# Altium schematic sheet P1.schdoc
size 297 x 209 mm; Symbol: Drawing-Symbol_A4; Company: 嘉立创EDA; Version: V1.0; Page Size: A4; @Project Name: 模拟前端处理电路; @Update Date: 2026-04-09; @Create Date: 2026-04-09; Device: Drawing-Symbol_A4; @Board Name: Board1; @Page Name: P1; @Create Time: 13:26:56; @Page Count: 1; @Page No: 1; @Schematic Name: Schematic1; @Update Time: 13:26:56; @Assembly Variant: Basic; Border: 1; Title Block Position: 3; Size: A4; Width: 1170; Height: 825; Region Start: 1; X Region Count: 6; Y Region Count: 4; Blade Width: 10; Title Block: 1
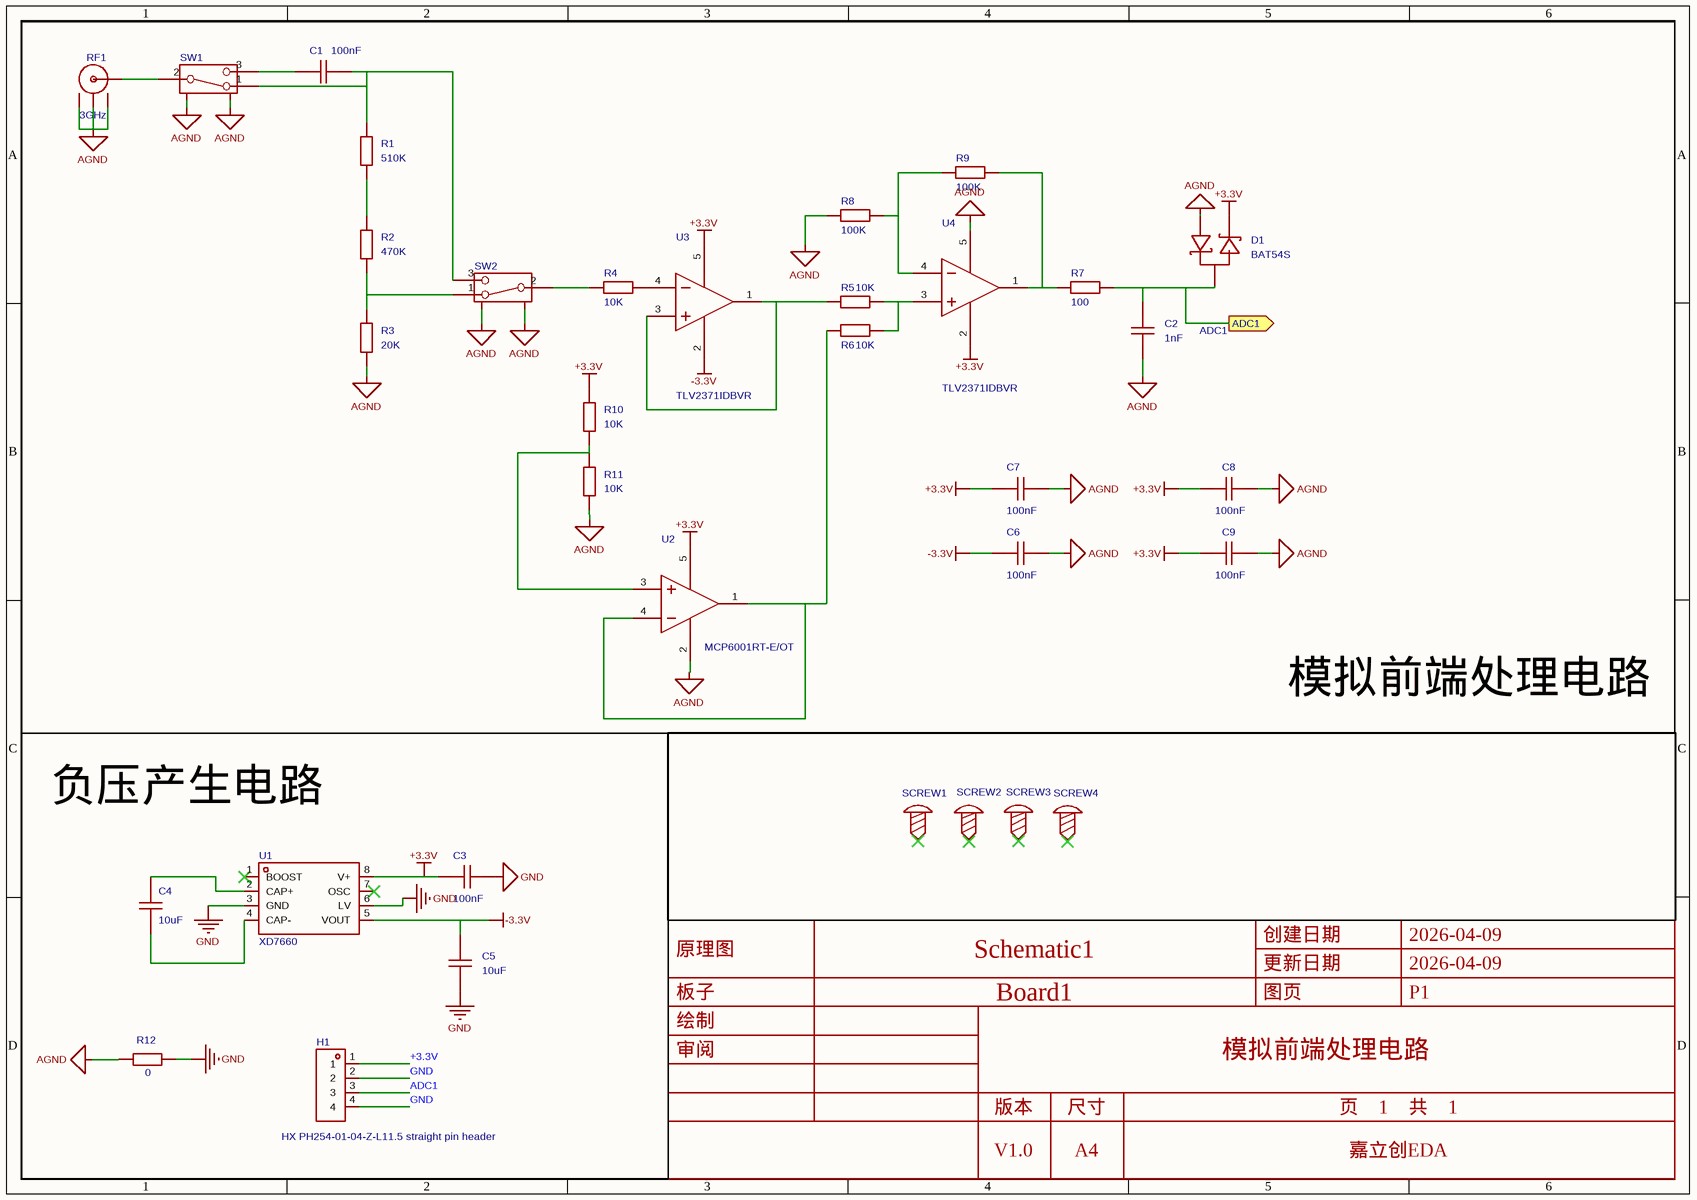
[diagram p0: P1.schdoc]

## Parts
C1  100nF  [C0603]
C2  1nF  [C0603]
C3  100nF  [C0603]
C4  10uF  [C0603]
C5  10uF  [C0603]
C6  100nF  [C0603]
C7  100nF  [C0603]
C8  100nF  [C0603]
C9  100nF  [C0603]
D1  BAT54S  [SOT-23-3_L2.9-W1.3-P1.90-LS2.4-BR]
H1  HX PH254-01-04-Z-L11.5 straight pin header  [HDR-TH_4P-HX-PH254-01-04-Z-L11.5]
R1  510K  [R0603]
R2  470K  [R0603]
R3  20K  [R0603]
R4  10K  [R0603]
R5  10K  [R0603]
R6  10K  [R0603]
R7  100  [R0603]
R8  100K  [R0603]
R9  100K  [R0603]
R10  10K  [R0603]
R11  10K  [R0603]
R12  0  [R0603]
RF1  3GHz  [ANT-TH_KH-BNC75-3511]
SCREW1  (no value)  [M2螺丝]
SCREW2  (no value)  [M2螺丝]
SCREW3  (no value)  [M2螺丝]
SCREW4  (no value)  [M2螺丝]
SW1  (no value)  [拨动开关_侧]
SW2  (no value)  [拨动开关_侧]
U1  XD7660  [DIP-8_L9.7-W6.4-P2.54-LS7.6-BL]
U2  MCP6001RT-E/OT  [SOT-23-5_L2.9-W1.6-P0.95-LS2.8-BR]
U3  TLV2371IDBVR  [SOT-23-5_L3.0-W1.7-P0.95-LS2.8-BR]
U4  TLV2371IDBVR  [SOT-23-5_L3.0-W1.7-P0.95-LS2.8-BR]

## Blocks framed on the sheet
模拟前端处理电路: C1 C2 C6-C9 D1 R1-R11 RF1 SW1 SW2 U2-U4
负压产生电路: C3-C5 H1 R12 U1

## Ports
ADC1 (out)

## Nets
+3.3V: C3.1 C7.2 C8.2 C9.2 D1.2(K2) H1.1 R10.2 U1.8(V+) U2.5(VSS) U3.5(VDD) U4.2(GND)
-3.3V: C5.2 C6.2 U1.5(VOUT) U3.2(GND)
AGND: C2.1 C6.1 C7.1 C8.1 C9.1 D1.1(K1) R3.1 R8.1 R11.1 R12.1 RF1.2 RF1.3 RF1.4 SW1.4 SW1.5 SW2.4 SW2.5 U2.2(VDD) U4.5(VDD)
GND: C3.2 C5.1 H1.2 H1.4 R12.2 U1.3(GND) U1.6(LV)
ADC1: C2.2 D1.3(A) H1.3 R7.2 ; port ADC1
NetC1_1: C1.1 SW1.3
NetC1_2: C1.2 R1.2 SW1.1 SW2.3
NetC4_1: C4.1 U1.4(CAP-)
NetC4_2: C4.2 U1.2(CAP+)
NetR1_1: R1.1 R2.2
NetR2_1: R2.1 R3.2 SW2.1
NetR4_1: R4.1 SW2.2
NetR4_2: R4.2 U3.4(IN-)
NetR5_1: R5.1 U3.1(OUT) U3.3(IN+)
NetR5_2: R5.2 R6.2 U4.3(IN+)
NetR6_1: R6.1 U2.1(VOUT) U2.4(VIN-)
NetR7_1: R7.1 R9.2 U4.1(OUT)
NetR8_2: R8.2 R9.1 U4.4(IN-)
NetR10_1: R10.1 R11.2 U2.3(VIN+)
NetRF1_1: RF1.1(OUT) SW1.2

Not connected (* = marked no-connect by the designer): SCREW1 1*; SCREW2 1*; SCREW3 1*; SCREW4 1*; U1 1(BOOST)* 7(OSC)*

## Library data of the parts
C1-C5 = CAP_0603: Symbol: Capacitance; ConvertToPcb: yes; ModelId: ac125912035d415993ca9572d50418b10819f05c4eef4c71ace90d822a990e87; ModelName: C0603_L1.6-W0.8-H0.8; ModelTransform: 62.992,31.496,0,0,0,0,0,0,0
C6-C9 = CAP_0603: Symbol: Capacitance; 3D Model: ac125912035d415993ca9572d50418b10819f05c4eef4c71ace90d822a990e87; 3D Model Transform: 62.992,31.496,0,0,0,0,0,0,0; ConvertToPcb: yes; ModelName: C0603_L1.6-W0.8-H0.8
D1 = BAT54S_C7420333: 二极管配置:1对串联式;正向压降(Vf):400mV@10mA;直流反向耐压(Vr):30V;整流电流:200mA;; Manufacturer: R+O(宏嘉诚); AddInBom: yes; ModelId: c62791f0466c4ae2a892c056b845b0ca0819f05c4eef4c71ace90d822a990e87; ModelName: SOT-23-3P_L2.9-W1.3-H1.0-LS2.4-P0.95; ModelTransform: 98.425,114.173,0,180,0,0,0.0005,-0.0005,0; Diode Configuration: 1对串联式; Voltage - DC Reverse(Vr): 30V; Current - Rectified: 200mA; Reverse Leakage Current (Ir): 2uA@30V; Non-Repetitive Peak Forward Surge Current: 600mA
H1 = HX PH254-01-04-Z-L11.5 straight pin header: 插针结构:1x4P;间距:2.54mm;圆针/方针:方针;安装方式:直插;排数:单排;总PIN位数:4P;额定电流:3A;额定电压:1kV;配合针长度:6mm;塑高:2.5mm;端接针长度:3mm;触头材质:黄铜;触头镀层:金;工作温度:-40℃~+105℃;; Manufacturer: hanxia(韩下); AddInBom: yes; ModelId: 8a04245d30e54eb999146b73785c6ab00819f05c4eef4c71ace90d822a990e87; ModelTransform: 392.519,98.425,0,0,0,0,0,0,-118.11; Pin Structure: 1x4P; Pitch: 2.54mm; Circluar Pins/Square Pins: 方针; Current Rating: 3A; Voltage Rating (Max): 1kV
R1-R11 = Res_0603: Symbol: 电阻; ConvertToPcb: yes; ModelId: fc143cca1e79419f9cd78b61e9279f080819f05c4eef4c71ace90d822a990e87; ModelTransform: 31.8897,63.7794,0,90,0,0,0,0,0
R12 = Res_0603: Symbol: 电阻; 3D Model: fc143cca1e79419f9cd78b61e9279f080819f05c4eef4c71ace90d822a990e87; 3D Model Transform: 31.8897,63.7794,0,90,0,0,0,0,0; ConvertToPcb: yes
RF1 = KH-BNC75-3511: 连接器类型:板端;接口类型:内孔;端口数量:1;接口直径:9.5mm;接口长度/高度:-;频率:3GHz;射频系列:BNC;阻抗:75Ω;样式:弯头;工作温度:-55℃~+155℃;; Manufacturer: kinghelm(金航标); AddInBom: yes; ModelId: ad62c497f6fc4a689331b26e51ab1d1d0819f05c4eef4c71ace90d822a990e87; ModelTransform: 578.739,1397.635,0,180,0,0,0,-522.717,-157.48; Connector Type: 板端; Interface: 内孔; Number of Ports: 1; Interface Diameter: 9.5mm; RF Series: BNC; Impedance: 75Ω; Style: 弯头
SCREW1-SCREW4 = M2螺丝: Symbol: 螺丝孔; ConvertToPcb: yes
SW1 SW2 = 拨动开关_侧: Symbol: 拨动开关; ConvertToPcb: yes; ModelId: 10ea2cc5ba004a75b38812aadef1031f0819f05c4eef4c71ace90d822a990e87; ModelName: SW-TH_SK-12D07-VG3; ModelTransform: 337.98,287.46,295.24,0,0,0,0,-57,-110
U1 = XD7660: 电荷泵 同步整流：否 输出通道数：1 输入电压：1.5V~12V 输出电压：-12V~-1.5V 输出电流(最大值)：45mA 开关频率：35kHz 芯片 电压转换器 50/管 初级输入电压: 12V 输出数: 1 输出电压: 22.8V 输出电流: 20mA; Manufacturer: XINLUDA(信路达); AddInBom: yes; ModelId: 5746b540d01a4d1b9eb6b4f989297bc70819f05c4eef4c71ace90d822a990e87; ModelName: DIP-8_L9.8-W6.6-H3.5-LS7.62-P2.54; ModelTransform: 385.826,311.8104,0,0,0,0,0,0,-118.11; Operating Voltage: 1.5V~10V; Quiescent Current: 160uA; Output Resistance: 60Ω; Energy Efficiency: 98%; Function: 反相; Output Voltage: -10V~-1.5V
U2 = MCP6001RT-E/OT: 放大器数:单路;轨到轨:轨到轨输入,轨到轨输出;增益带宽积(GBP):1MHz;输入失调电压(Vos):4.5mV;压摆率(SR):600V/ms;输入偏置电流(Ib):1pA;; Manufacturer: MICROCHIP(美国微芯); AddInBom: yes; ModelId: 7ba65df16e7b4570af156e925f9c37fe0819f05c4eef4c71ace90d822a990e87; ModelTransform: 114.173,114.173,0,90,0,0,0,0,0; Number of Channels: 单路; Maximum Power Supply Range (Vdd-Vss): 7V; Gain Bandwidth Product: 1MHz; Vos - Input Offset Voltage: 4.5mV; Input Offset Voltage Drift(Vos TC): 2uV/℃; Ib - Input Bias Current: 1pA; Noise density(eN): 28nV/√Hz@1kHz; Common Mode Rejection Ratio(CMRR): 76dB; Quiescent Current: 100uA; Output Current: 23mA; Single supply: 1.8V~6V
U3 U4 = TLV2371IDBVR: 放大器数:单路;轨到轨:轨到轨输入,轨到轨输出;增益带宽积(GBP):3MHz;输入失调电压(Vos):4.5mV;压摆率(SR):2.1V/us;输入偏置电流(Ib):1pA;; Manufacturer: TI(德州仪器); AddInBom: yes; ModelId: 0a2a1b8f50944f73965918ad6e5fe1670819f05c4eef4c71ace90d822a990e87; ModelName: SOT-23-5_L2.9-W1.6-H1.1-LS2.8-P0.95; ModelTransform: 114.173,109.636,0,180,0,0,0,0,0; Number of Channels: 单路; Maximum Power Supply Range (Vdd-Vss): 16V; Gain Bandwidth Product: 3MHz; Vos - Input Offset Voltage: 4.5mV; Input Offset Voltage Drift(Vos TC): 2uV/℃; Ib - Input Bias Current: 1pA; Noise density(eN): 35nV/√Hz@10kHz; Common Mode Rejection Ratio(CMRR): 84dB; Quiescent Current: 560uA; Output Current: 16mA; Single supply: 2.7V~16V; Dual Supply: 1.35V~8V；-8V~-1.35V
